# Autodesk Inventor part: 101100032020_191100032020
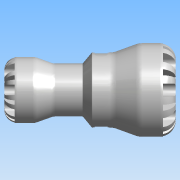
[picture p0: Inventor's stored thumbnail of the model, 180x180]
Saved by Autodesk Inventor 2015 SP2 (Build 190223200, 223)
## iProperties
Created: 2016-12
Part Number: 101100032020_191100032020
Material: PVC-Piping
Description: PLASSON REDUCING COUPLING 32X20 SERIES 1
Document SubType Name: Modeling
Designer: KIM
Mass: 113.204 g
Surface Area: 237.851 cm^2
Volume: 80.8599 cm^3
Density: 1.4 g/cm^3
Appearance: Smooth - White
Author: KIM
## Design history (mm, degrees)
derived "1011.ipt"
feature "Solid1::1011.ipt"
tag "TaggingFeature1"
body "Solid1"
other parameters: "d0" = 106, "d2" = 22.68, "d3" = 32, "d4" = 58, "d5" = 38.4, "d6" = 54, "d7" = 2.66667, "d8" = 41, "d10" = 25, "d11" = 18.9, "d12" = 45, "d13" = 1.66667, "d14" = 46.4, "d15" = 32.8, "d16" = 20 deg, "d17" = 20 deg, "d18" = 130 deg, "d22" = 7.84, "d25" = 7.84, "d26" = 0, "d28" = 360 deg, "d30" = 8 deg, "d31" = 0.64, "d32" = 8 deg, "d33" = 0.64, "d35" = 0, "d37" = 360 deg, "d39" = 6.4, "d42" = 6.4, "d43" = 0, "d45" = 360 deg, "d47" = 0.4, "d48" = 8 deg, "d49" = 8 deg, "d50" = 0.4, "d52" = 0, "d54" = 360 deg, "d56" = 8.2, "d57" = 11.6, "d58" = 0.5, "d60" = 6.96, "d61" = 8, "d62" = 12.96, "d63" = 0, "d66" = 0, "d68" = 360 deg, "d75" = 5.4501, "d77" = 45.24, "d78" = 0.58, "d_" = 32, "E_" = 58, "H_" = 106, "l_" = 54, "E1" = 41, "l1" = 45, "Plasson" = 1, "d20" = 8, "d21" = 9.8, "d23" = 58, "d24" = 38.4, "d40" = 41, "d41" = 25, "d59" = 10.90021
